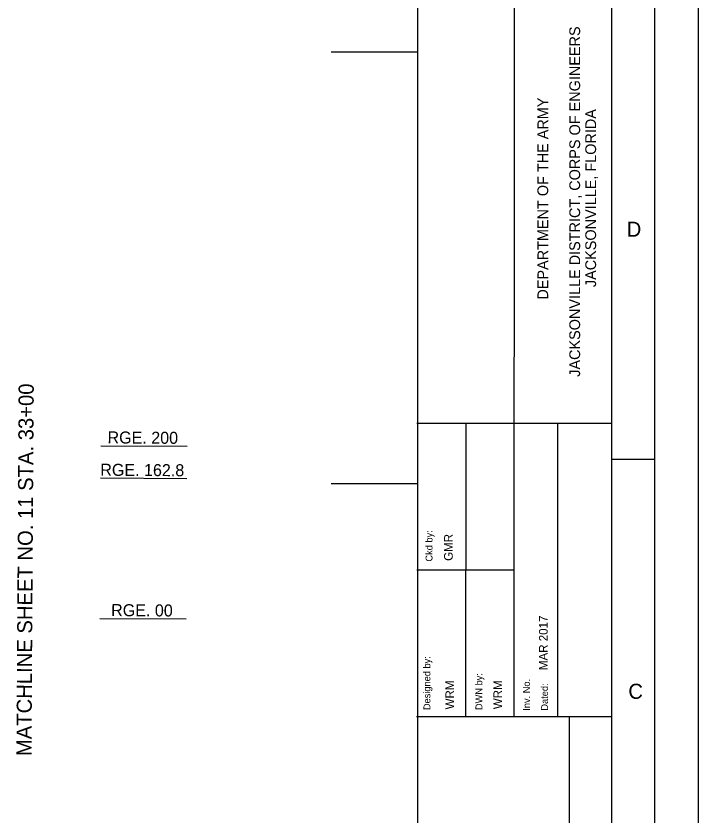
# Model space of a CAD drawing. Extents: x 517982 to 522382, y 1296329 to 1299729.
# Drawn here: x 521591 to 522381, y 1297616 to 1298542 of the extents above; entities that cross this region are included whole.
import ezdxf

# ---------------------------------------------------------------- set-up
doc = ezdxf.new("R2010")
doc.units = 0
for name, color, linetype in [('G-ANNO-NPLT', 7, 'Continuous'), ('G-ANNO-TEXT-DRWG', 7, 'Continuous'), ('G-ANNO-TEXT-PROJ', 7, 'Continuous'), ('G-ANNO-TEXT-TTLB', 7, 'Continuous'), ('G-ANNO-TTLB', 7, 'Continuous'), ('V-ALGN-TEXT', 7, 'Continuous'), ('V-ANNO-MATC-IDEN', 7, 'Continuous'), ('V-TOPO-COOR-STAT', 7, 'Continuous')]:
    doc.layers.add(name, color=color, linetype=linetype)

msp = doc.modelspace()

# ---------------------------------------------------------------- linework, layer by layer
at = {"layer": 'G-ANNO-NPLT'}
msp.add_lwpolyline([(517981.52, 1299728.55), (522381.5, 1299728.55), (522381.5, 1296328.57), (517981.52, 1296328.57)], close=True, dxfattribs=at)
at = {"layer": 'G-ANNO-TTLB'}
for p, q in [((522056.47, 1299628.55), (522056.47, 1296428.57)), ((522168.34, 1297730.72), (522169, 1298590.29)), ((522055.7, 1298070.39), (522281.5, 1298070.39)), ((522112.39, 1297730.76), (522112.65, 1298070.39)), ((522218.53, 1298070.39), (522218.53, 1297730.72)), ((522331.5, 1298028.46), (522281.5, 1298028.46)), ((522055.7, 1297900.54), (522168.47, 1297900.54)), ((522055.28, 1297730.72), (522281.5, 1297730.72)), ((522232.2, 1297730.72), (522232.2, 1297379.33))]:
    msp.add_line(p, q, dxfattribs=at)
for points in [[(518031.52, 1296378.57), (522331.5, 1296378.57), (522331.5, 1299678.55), (518031.52, 1299678.55)], [(522281.5, 1299628.55), (518156.52, 1299628.55), (518156.52, 1296428.57), (522281.5, 1296428.57)]]:
    msp.add_lwpolyline(points, close=True, dxfattribs=at)
at = {"layer": 'V-ALGN-TEXT'}
for p, q in [((521689.33, 1298044.17), (521789.33, 1298043.56)), ((521689.19, 1298006.95), (521789.1, 1298006.34)), ((521688.11, 1297844.17), (521788.11, 1297843.56))]:
    msp.add_line(p, q, dxfattribs=at)
at = {"layer": 'V-TOPO-COOR-STAT'}
for p, q in [((522056.47, 1298500), (521956.47, 1298500)), ((522056.47, 1298000), (521956.47, 1298000))]:
    msp.add_line(p, q, dxfattribs=at)

# ---------------------------------------------------------------- texts
at = {"layer": 'G-ANNO-TEXT-DRWG'}
for s, p in [('GMR', (522097.22, 1297910.86)), ('WRM', (522098.74, 1297738.8)), ('WRM', (522154.37, 1297739.03))]:
    msp.add_text(s, height=10, rotation=90, dxfattribs=at).set_placement(p)
at = {"layer": 'G-ANNO-TEXT-PROJ'}
msp.add_text('MAR 2017', height=10, rotation=90, dxfattribs=at).set_placement((522207.23, 1297784.3))
at = {"layer": 'G-ANNO-TEXT-TTLB'}
for s, height, p in [('JACKSONVILLE DISTRICT, CORPS OF ENGINEERS', 12.5, (522244.87, 1298124.09)), ('DEPARTMENT OF THE ARMY', 12.5, (522207.87, 1298213.49)), ('JACKSONVILLE, FLORIDA', 12.5, (522263.37, 1298227.95)), ('Ckd by:', 8, (522073.75, 1297910.03)), ('Designed by:', 8, (522071.3, 1297737.98)), ('DWN by:', 8, (522131.52, 1297738.02)), ('Inv. No.', 8, (522186.74, 1297737.28)), ('Dated:', 8, (522207.56, 1297737.37))]:
    msp.add_text(s, height=height, rotation=90, dxfattribs=at).set_placement(p)
at = {"layer": 'G-ANNO-TTLB'}
for s, p in [('D', (522298.84, 1298286.28)), ('C', (522300.74, 1297751.05))]:
    msp.add_text(s, height=17.5, dxfattribs=at).set_placement(p)
at = {"layer": 'V-ALGN-TEXT'}
for s, p in [('RGE. 200', (521697.12, 1298046.9)), ('RGE. 162.8', (521688.75, 1298009.45)), ('RGE. 00', (521701.31, 1297846.87))]:
    msp.add_text(s, height=13.92, rotation=359.65012, dxfattribs=at).set_placement(p)
at = {"layer": 'V-ANNO-MATC-IDEN'}
msp.add_text('MATCHLINE SHEET NO. 11 STA. 33+00', height=17.52, rotation=89.65012, dxfattribs=at).set_placement((521609.04, 1297684.66))

doc.saveas('drawing.dxf')
